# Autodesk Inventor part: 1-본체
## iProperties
Created: 2015-01
Part Number: 1-본체
Document SubType Name: Modeling
Designer: Administrator
Density: 2.71 g/cm^3
Material: 알루미늄-6061
Mass: 1021.25 g
Surface Area: 1059.8 cm^2
Volume: 376.846 cm^3
Author: Administrator
